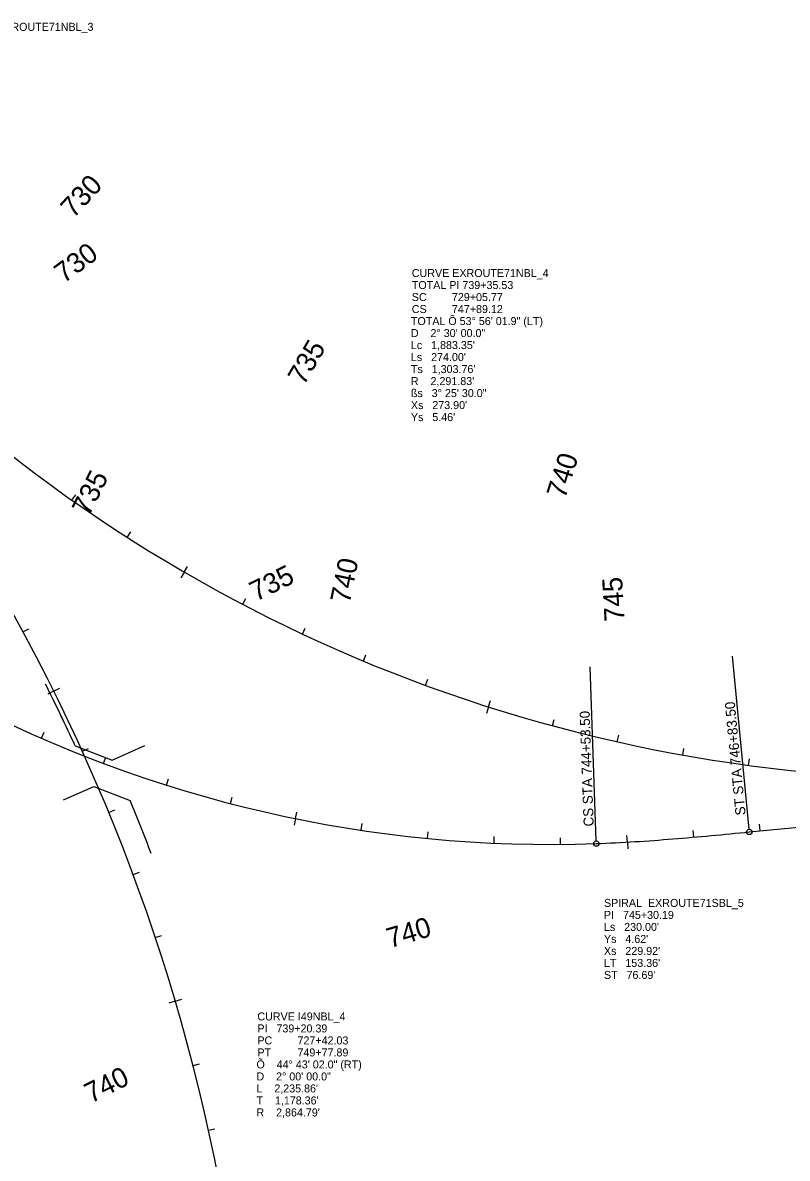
# Model space of a CAD drawing. Extents: x 2819977 to 2827606, y 116785 to 150320.
# Drawn here: x 2823483 to 2824629, y 144853 to 146556 of the extents above; entities that cross this region are included whole.
import ezdxf

# ---------------------------------------------------------------- set-up
doc = ezdxf.new("R2010")
doc.units = 0
for name, color, linetype in [('Default', 7, 'Continuous'), ('Modeling-Contours-Major-Existing', 7, 'Continuous'), ('Modeling-Contours-Minor-Existing', 7, 'Continuous'), ('Modeling-Flow Arrows-Existing', 7, 'Continuous'), ('Modeling-Triangle Verticies-Existing', 7, 'Continuous'), ('Roadway-Walls', 7, 'Continuous')]:
    doc.layers.add(name, color=color, linetype=linetype)

msp = doc.modelspace()

# ---------------------------------------------------------------- linework, layer by layer
at = {"layer": 'Default'}
for centre, radius, start, end in [((2824274.6, 147233.3), 1909.9, 212.4335, 272.05), ((2820963.6, 144279.3), 2864.8, 356.8489, 41.5661), ((2824876.4, 147713.4), 2291.8, 224.9911, 272.075), ((2820963.6, 144279.3), 2858.4, 25.4438, 26.7068)]:
    msp.add_arc(centre, radius, start, end, dxfattribs=at)
msp.add_open_spline([(2824342.9, 145324.7), (2824362.1, 145325.4), (2824400.4, 145327.3), (2824457.7, 145331.6), (2824515, 145336.6), (2824553.1, 145340.3), (2824572.2, 145342.1)], degree=3, dxfattribs=at)
at = {"layer": 'Modeling-Contours-Major-Existing'}
for p, q in [((2823556.8, 145839.5), (2823562.6, 145847.7)), ((2823639.8, 145783.8), (2823645.2, 145792.2)), ((2823725.1, 145731.7), (2823720.1, 145723)), ((2823725.1, 145731.7), (2823730.2, 145740.3)), ((2823812.7, 145683.3), (2823817.3, 145692.2)), ((2823902.2, 145638.9), (2823906.5, 145647.9)), ((2823993.7, 145598.4), (2823997.5, 145607.6)), ((2824086.8, 145561.9), (2824090.2, 145571.3)), ((2824181.4, 145529.5), (2824178.3, 145519.9)), ((2824181.4, 145529.5), (2824184.4, 145539)), ((2824277.3, 145501.2), (2824279.9, 145510.9)), ((2823511.4, 145482.6), (2823515.4, 145491.8)), ((2824374.3, 145477.2), (2824376.5, 145487)), ((2824472.4, 145457.4), (2824474.1, 145467.3)), ((2823604, 145445), (2823607.5, 145454.4)), ((2824571.1, 145442), (2824572.5, 145451.9)), ((2823698.5, 145412.4), (2823701.6, 145421.9)), ((2823794.6, 145384.8), (2823797.1, 145394.4)), ((2824572.2, 145342.1), (2825086.6, 145391.7)), ((2823892, 145362.2), (2823894, 145372)), ((2823892, 145362.2), (2823890, 145352.4)), ((2823990.5, 145344.7), (2823992, 145354.6)), ((2824588.6, 145343.7), (2824587.7, 145353.7)), ((2824089.7, 145332.4), (2824090.7, 145342.4)), ((2824389.4, 145326.9), (2824388.8, 145336.9)), ((2824489.1, 145334.3), (2824488.2, 145344.3)), ((2824189.5, 145325.4), (2824189.9, 145335.3)), ((2824289.4, 145323.5), (2824289.4, 145333.5)), ((2824389.4, 145326.9), (2824389.9, 145316.9))]:
    msp.add_line(p, q, dxfattribs=at)
for centre, radius, start, end in [((2824274.6, 147233.3), 1909.9, 212.4335, 272.05), ((2824876.4, 147713.4), 2291.8, 224.9911, 272.075)]:
    msp.add_arc(centre, radius, start, end, dxfattribs=at)
msp.add_open_spline([(2824342.9, 145324.7), (2824362.1, 145325.4), (2824400.4, 145327.3), (2824457.7, 145331.6), (2824515, 145336.6), (2824553.1, 145340.3), (2824572.2, 145342.1)], degree=3, dxfattribs=at)
at = {"layer": 'Modeling-Contours-Minor-Existing'}
for p, q in [((2824571.8, 145346.1), (2824546.8, 145605.9)), ((2824342.8, 145328.7), (2824333.4, 145589.5))]:
    msp.add_line(p, q, dxfattribs=at)
for centre in [(2824572.2, 145342.1), (2824342.9, 145324.7)]:
    msp.add_circle(centre, 4, dxfattribs=at)
at = {"layer": 'Modeling-Flow Arrows-Existing'}
for p, q in [((2823483.4, 145642.2), (2823492.2, 145646.9)), ((2823529.4, 145553.4), (2823538.4, 145557.8)), ((2823529.4, 145553.4), (2823520.5, 145548.9)), ((2823572.3, 145463.1), (2823581.4, 145467.2)), ((2823612.1, 145371.3), (2823621.3, 145375.1)), ((2823648.6, 145278.2), (2823657.9, 145281.7)), ((2823681.8, 145183.9), (2823691.3, 145187)), ((2823711.7, 145088.5), (2823702.1, 145085.6)), ((2823711.7, 145088.5), (2823721.3, 145091.3)), ((2823738.3, 144992.1), (2823747.9, 144994.6)), ((2823761.4, 144894.8), (2823771.2, 144896.9))]:
    msp.add_line(p, q, dxfattribs=at)
msp.add_arc((2820963.6, 144279.3), 2864.8, 356.8489, 41.5661, dxfattribs=at)
at = {"layer": 'Roadway-Walls'}
for p, q in [((2823561.5, 145471.3), (2823616.9, 145449.9)), ((2823616.9, 145449.9), (2823666.3, 145471.7)), ((2823543.9, 145390.5), (2823589.8, 145410.3)), ((2823543.9, 145390.5), (2823589.8, 145410.3)), ((2823589.8, 145410.3), (2823644, 145389.4)), ((2823589.8, 145410.3), (2823644, 145389.4))]:
    msp.add_line(p, q, dxfattribs=at)
for radius, start, end in [(2858.4, 24.6466, 26.7068), (2901.2, 20.8068, 22.4964), (2901.2, 20.8068, 22.4964)]:
    msp.add_arc((2820963.6, 144279.3), radius, start, end, dxfattribs=at)

# ---------------------------------------------------------------- texts
at = {"layer": 'Modeling-Contours-Major-Existing'}
for s, rotation, p in [(' 730', 47.3469, (2823551.4, 146253)), (' 735', 59.8469, (2823898.9, 146000.8)), (' 740', 72.3469, (2824292.7, 145829.9)), (' 735', 63.445, (2823577.3, 145804.5)), (' 740', 78.445, (2823970.8, 145672.7)), (' 745', 93.304, (2824385.9, 145647.2))]:
    msp.add_text(s, height=30, rotation=rotation, dxfattribs=at).set_placement(p)
at = {"layer": 'Modeling-Contours-Minor-Existing'}
for s, rotation, p in [('ST STA 746+83.50', 95.5, (2824566.7, 145367.7)), ('CS STA 744+53.50', 92.05, (2824339, 145350.6))]:
    msp.add_text(s, height=15, rotation=rotation, dxfattribs=at).set_placement(p)
at = {"layer": 'Modeling-Flow Arrows-Existing'}
for s, rotation, p in [(' 730', 36.4068, (2823535.6, 146157.4)), (' 735', 26.4068, (2823822.7, 145682.3)), (' 740', 16.4068, (2824022.9, 145164.5)), (' 740', 26.4209, (2823575.2, 144930))]:
    msp.add_text(s, height=30, rotation=rotation, dxfattribs=at).set_placement(p)
at = {"layer": 'Modeling-Triangle Verticies-Existing'}
for s, p in [('SPIRAL  EXROUTE71NBL_3', (2823378.6, 146543.4)), ('CURVE EXROUTE71NBL_4', (2824066.3, 146174.2)), ('TOTAL PI 739+35.53', (2824066.3, 146156.2)), ('SC', (2824066.3, 146138.2)), ('729+05.77', (2824126.4, 146138.2)), ('CS', (2824066.3, 146120.2)), ('747+89.12', (2824126.4, 146120.2)), ('TOTAL Õ 53%%d 56\' 01.9" (LT)', (2824064.9, 146102.2)), ('D    2%%d 30\' 00.0"', (2824064.9, 146084.2)), ("Lc   1,883.35'", (2824064.9, 146066.2)), ("Ls   274.00'", (2824064.9, 146048.2)), ("Ts   1,303.76'", (2824064.9, 146030.2)), ("R    2,291.83'", (2824064.9, 146012.2)), ('ßs   3%%d 25\' 30.0"', (2824064.9, 145994.2)), ("Xs   273.90'", (2824064.9, 145976.2)), ("Ys   5.46'", (2824064.9, 145958.2)), ('SPIRAL  EXROUTE71SBL_5', (2824354.3, 145229.7)), ('PI   745+30.19', (2824354.3, 145211.7)), ("Ls   230.00'", (2824354.3, 145193.7)), ("Ys   4.62'", (2824354.3, 145175.7)), ("Xs   229.92'", (2824354.3, 145157.7)), ("LT   153.36'", (2824354.3, 145139.7)), ("ST   76.69'", (2824354.3, 145121.7)), ('CURVE I49NBL_4', (2823834.8, 145059.5)), ('PI   739+20.39', (2823834.8, 145041.5)), ('PC', (2823834.8, 145023.5)), ('727+42.03', (2823894.9, 145023.5)), ('PT', (2823834.8, 145005.5)), ('749+77.89', (2823894.9, 145005.5)), ('Õ    44%%d 43\' 02.0" (RT)', (2823833.4, 144987.5)), ('D    2%%d 00\' 00.0"', (2823833.4, 144969.5)), ("L    2,235.86'", (2823833.4, 144951.5)), ("T    1,178.36'", (2823833.4, 144933.5)), ("R    2,864.79'", (2823833.4, 144915.5))]:
    msp.add_text(s, height=12, dxfattribs=at).set_placement(p)

doc.saveas('drawing.dxf')
